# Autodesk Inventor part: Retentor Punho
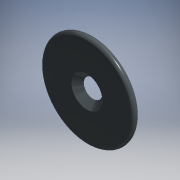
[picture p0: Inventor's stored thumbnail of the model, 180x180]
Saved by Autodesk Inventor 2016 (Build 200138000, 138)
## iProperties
Created: 2016-02
Part Number: Retentor Punho
Material: Iron, Ductile
Document SubType Name: Modeling
Designer: Vertex
Density: 7.15 g/cm^3
Appearance: Iron Gray
Mass: 9.08938 g
Surface Area: 14.8469 cm^2
Volume: 1.27124 cm^3
Author: Vertex
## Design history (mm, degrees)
sketch "Sketch1"
  geometry: C1 r 15 at (0, 0); 1 further point
  constraints: 1 centre point, 1 coincident
  dimensions: "d0" = 30 diameter of C1
extrude "Extrusion1" new body sketch "Sketch1" distance "d1" = 2; taper "d2" = 0 deg
hole "Hole1" diameter "d5" = 4.13; stored, may be unused: countersink angle "d9" = 90 deg, drill point angle "d11" = 118 deg; dims "d3" = 10, "d4" = 10, "d6" = 10, "d7" = 10, "d8" = 2.5, "d10" = 14.2
fillet "Fillet1" dims "d12" = 1
body "Solid1"
